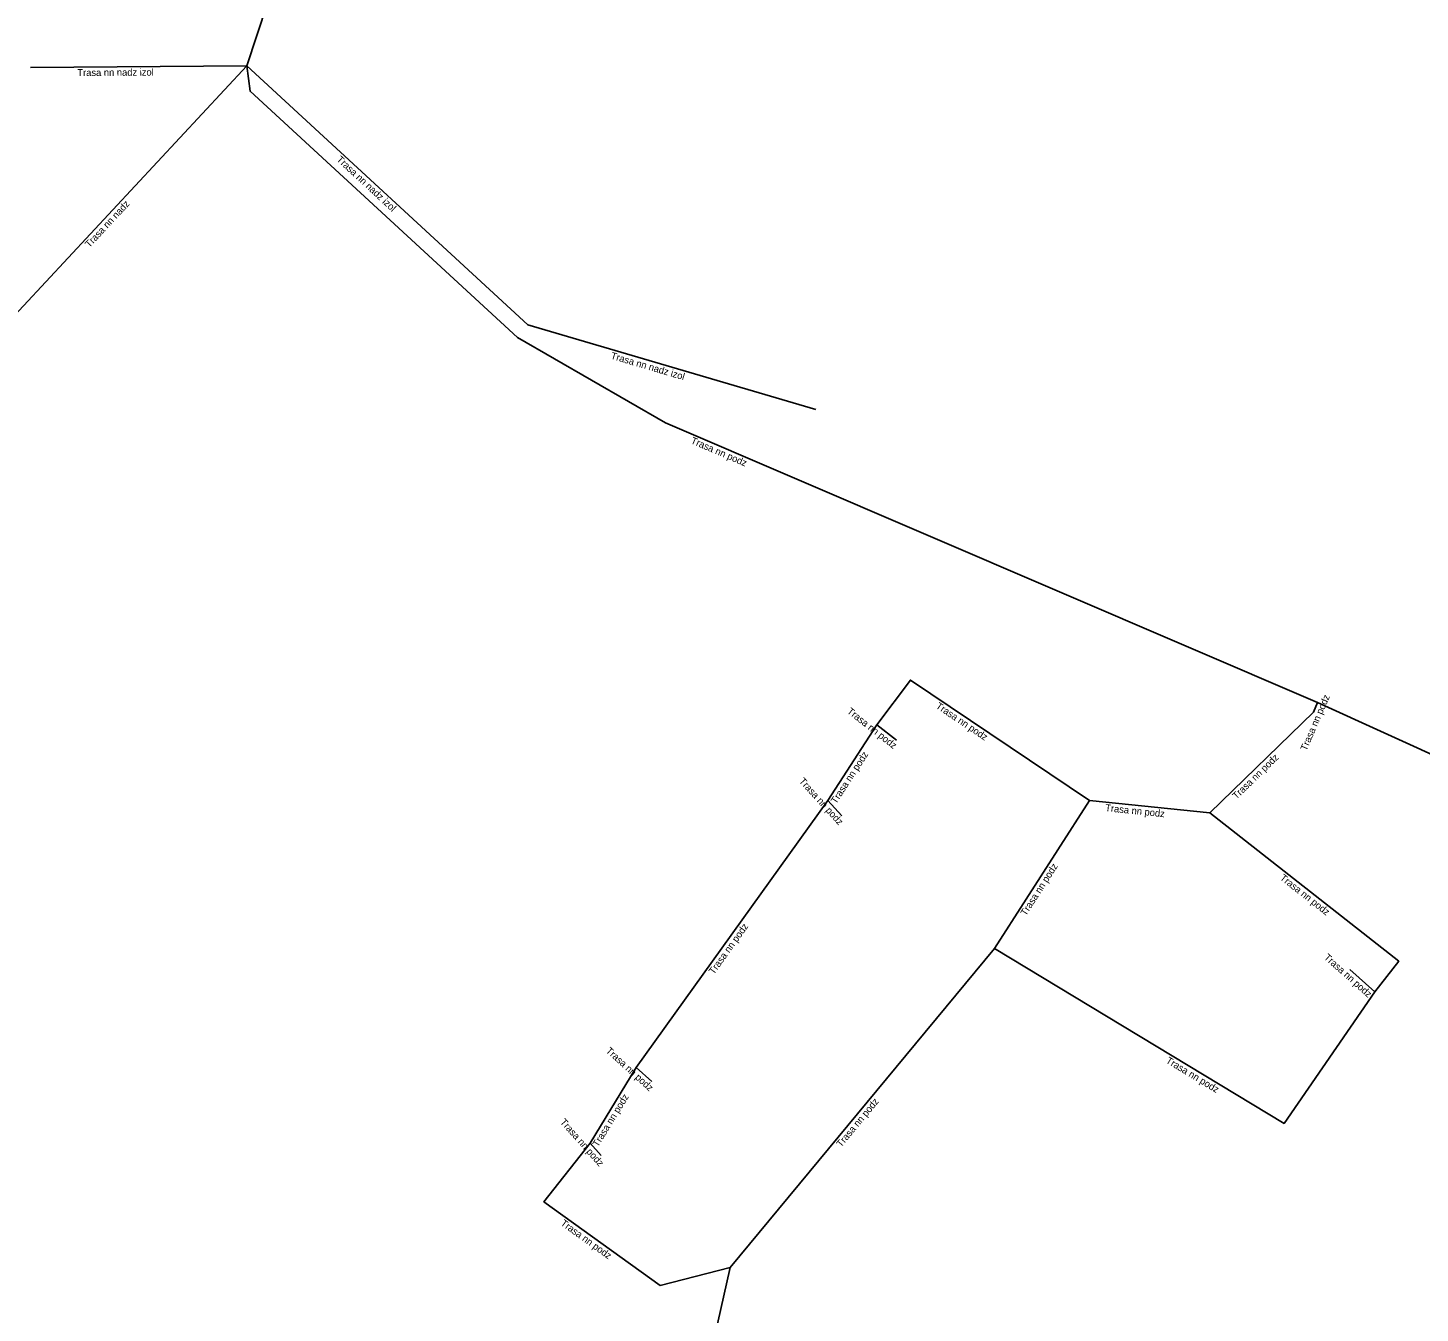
# Model space of a CAD drawing. Extents: x -747466 to -746981, y -1017505 to -1017087.
# Drawn here: x -747316 to -747216.5, y -1017425.2 to -1017333.3 of the extents above; entities that cross this region are included whole.
import ezdxf

# ---------------------------------------------------------------- set-up
doc = ezdxf.new("R2010")
doc.units = 0
doc.layers.add('Popiskový text - Ostatní atributy Trasy', color=7, linetype='Continuous')
doc.layers.add('Spojnice NN', color=7, linetype='Continuous')

msp = doc.modelspace()

# ---------------------------------------------------------------- linework, layer by layer
at = {"layer": 'Spojnice NN'}
for points in [[(-747290.862, -1017307.201), (-747300.334, -1017335.974)], [(-747300.334, -1017335.974), (-747319.51, -1017356.568)], [(-747300.334, -1017335.974), (-747315.8, -1017336.1)], [(-747223.8, -1017381.5), (-747270.4, -1017361.5), (-747281, -1017355.4), (-747300.1, -1017337.8), (-747300.334, -1017335.974)], [(-747300.334, -1017335.974), (-747280.261, -1017354.505)], [(-747280.261, -1017354.505), (-747259.674, -1017360.568)], [(-747240.1, -1017388.5), (-747252.9, -1017379.9), (-747255.3, -1017383.1)], [(-747224.1, -1017382.2), (-747231.5, -1017389.4)], [(-747224.1, -1017382.2), (-747223.8, -1017381.5)], [(-747223.8, -1017381.5), (-747199.2, -1017392.7), (-747196.38, -1017395.889)], [(-747255.3, -1017383.1), (-747258.8, -1017388.5)], [(-747255.3, -1017383.1), (-747253.9, -1017384.2)], [(-747258.8, -1017388.5), (-747272.5, -1017407.6)], [(-747258.8, -1017388.5), (-747257.8, -1017389.6)], [(-747246.9, -1017399.1), (-747240.1, -1017388.5)], [(-747231.5, -1017389.4), (-747240.1, -1017388.5)], [(-747231.5, -1017389.4), (-747218, -1017400), (-747219.7, -1017402.2)], [(-747265.8, -1017421.9), (-747246.9, -1017399.1)], [(-747219.7, -1017402.2), (-747226.2, -1017411.6), (-747246.9, -1017399.1)], [(-747219.7, -1017402.2), (-747221.5, -1017400.6)], [(-747272.5, -1017407.6), (-747275.8, -1017413)], [(-747272.5, -1017407.6), (-747271.4, -1017408.6)], [(-747275.8, -1017413), (-747279.1, -1017417.2), (-747270.8, -1017423.2), (-747265.8, -1017421.9)], [(-747275.8, -1017413), (-747275, -1017413.9)], [(-747268.2, -1017432.6), (-747265.8, -1017421.9)]]:
    msp.add_lwpolyline(points, dxfattribs=at)

# ---------------------------------------------------------------- texts
at = {"layer": 'Popiskový text - Ostatní atributy Trasy'}
for s, rotation, p in [('Trasa nn nadz izol', 0.46677, (-747312.452, -1017336.723)), ('Trasa nn nadz izol', 317.28741, (-747293.964, -1017342.739)), ('Trasa nn nadz', 47.04202, (-747311.591, -1017349.018)), ('Trasa nn nadz izol', 343.58997, (-747274.363, -1017356.92)), ('Trasa nn podz', 336.77174, (-747268.647, -1017362.959)), ('Trasa nn podz', 326.10383, (-747251.135, -1017381.869)), ('Trasa nn podz', 66.80141, (-747224.592, -1017385)), ('Trasa nn podz', 321.84277, (-747257.477, -1017382.217)), ('Trasa nn podz', 57.05078, (-747258.216, -1017388.795)), ('Trasa nn podz', 44.21518, (-747229.603, -1017388.461)), ('Trasa nn podz', 312.27369, (-747260.898, -1017387.158)), ('Trasa nn podz', 354.02568, (-747238.999, -1017389.269)), ('Trasa nn podz', 57.31945, (-747244.652, -1017396.8)), ('Trasa nn podz', 321.86152, (-747226.534, -1017394.126)), ('Trasa nn podz', 54.34898, (-747266.956, -1017400.986)), ('Trasa nn podz', 318.36646, (-747223.385, -1017399.795)), ('Trasa nn podz', 317.72631, (-747274.716, -1017406.464)), ('Trasa nn podz', 328.8737, (-747234.689, -1017407.233)), ('Trasa nn podz', 58.57043, (-747275.237, -1017413.325)), ('Trasa nn podz', 50.34306, (-747257.858, -1017413.338)), ('Trasa nn podz', 311.63354, (-747277.977, -1017411.53)), ('Trasa nn podz', 324.13715, (-747277.952, -1017418.832))]:
    msp.add_text(s, height=0.5, rotation=rotation, dxfattribs=at).set_placement(p)

doc.saveas('drawing.dxf')
